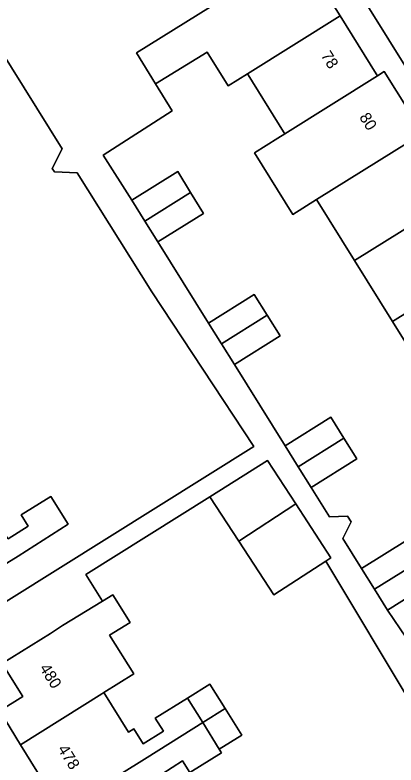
# Model space of a CAD drawing. Extents: x 159664 to 160323, y 385312 to 386115.
# Drawn here: x 159872.7 to 159905.9, y 385585.5 to 385650.9 of the extents above; entities that cross this region are included whole.
import ezdxf

# ---------------------------------------------------------------- set-up
doc = ezdxf.new("R2010")
doc.units = 0
for name, color, linetype in [('IMGEO_Erf', 7, 'Continuous'), ('IMGEO_Pand', 7, 'Continuous'), ('IMGEO_Pand_nummerreeks', 7, 'Continuous'), ('IMGEO_Voetpad_open', 7, 'Continuous')]:
    doc.layers.add(name, color=color, linetype=linetype)

msp = doc.modelspace()

# ---------------------------------------------------------------- linework, layer by layer
at = {"layer": 'IMGEO_Erf'}
for points in [[(159946.596, 385582.567), (159899.669, 385657.765), (159897.541, 385656.437), (159901.066, 385650.785), (159904.21, 385645.744), (159904.322, 385645.564), (159904.916, 385645.935), (159908.271, 385640.569)], [(159909.004, 385618.773), (159905.636, 385624.163), (159902.314, 385629.478), (159898.999, 385634.783), (159896.947, 385633.503), (159893.597, 385638.872), (159895.645, 385640.15), (159896.237, 385640.52), (159896.137, 385640.682), (159893.055, 385645.666), (159893.002, 385645.752), (159891.306, 385644.694), (159889.482, 385647.642), (159884.982, 385644.861), (159886.432, 385642.516), (159880.411, 385638.648), (159882.922, 385634.74), (159886.912, 385637.224), (159888.043, 385635.407), (159889.175, 385633.59), (159885.185, 385631.105), (159889.598, 385624.037), (159893.579, 385626.535), (159894.71, 385624.733), (159895.842, 385622.931), (159891.861, 385620.432), (159896.265, 385613.331), (159900.248, 385615.826), (159901.381, 385614.016), (159902.515, 385612.206), (159898.531, 385609.712), (159900.142, 385607.157), (159901.713, 385607.207), (159902.04, 385606.724), (159901.315, 385605.272), (159902.94, 385602.661), (159906.93, 385605.145)], [(159872.124, 385605.243), (159873.887, 385606.344), (159873.274, 385607.325), (159875.856, 385608.938), (159877.358, 385606.535), (159872.995, 385603.734), (159872.011, 385603.118)], [(159907.52, 385590.473), (159899.833, 385603.309), (159895.3, 385600.355), (159892.24, 385605.051), (159889.724, 385608.912), (159878.895, 385602.141), (159880.347, 385599.819), (159881.256, 385600.374), (159882.76, 385597.969), (159880.976, 385596.854), (159883.079, 385593.489), (159880.464, 385591.853), (159882.616, 385588.411), (159883.085, 385588.704), (159883.906, 385587.39), (159885.662, 385588.488), (159884.955, 385589.619), (159887.761, 385591.373), (159889.723, 385592.599), (159891.06, 385590.46), (159892.503, 385588.152), (159890.541, 385586.926), (159890.741, 385586.607), (159887.979, 385584.88), (159887.345, 385585.894), (159885.531, 385584.76)], [(159909.182, 385601.526), (159905.191, 385599.043), (159906.855, 385596.601)], [(159875.549, 385583.563), (159873.206, 385587.314), (159871.373, 385590.249), (159873.403, 385591.515), (159871.612, 385594.38), (159866.206, 385591), (159867.78, 385588.482), (159889.403, 385553.858)]]:
    msp.add_lwpolyline(points, dxfattribs=at)
msp.add_lwpolyline([(159884.653, 385626.763), (159878.162, 385637.111), (159876.173, 385637.213), (159875.976, 385637.489), (159876.848, 385639.206), (159870.177, 385649.841), (159864.753, 385646.292), (159863.207, 385648.655), (159868.631, 385652.204), (159868.368, 385652.606), (159839.054, 385634.423), (159863.871, 385594.734), (159893.561, 385613.299)], close=True, dxfattribs=at)
at = {"layer": 'IMGEO_Pand'}
for points in [[(159901.066, 385650.785), (159897.541, 385656.437), (159883.314, 385647.559), (159884.982, 385644.861), (159889.482, 385647.642), (159891.306, 385644.694), (159893.002, 385645.752)], [(159904.322, 385645.564), (159904.21, 385645.744), (159901.066, 385650.785), (159893.002, 385645.752), (159893.055, 385645.666), (159896.137, 385640.682), (159896.237, 385640.52)], [(159908.271, 385640.569), (159904.916, 385645.935), (159904.322, 385645.564), (159896.237, 385640.52), (159895.645, 385640.15), (159893.597, 385638.872), (159896.947, 385633.503), (159898.999, 385634.783), (159907.084, 385639.828)], [(159907.183, 385639.669), (159907.084, 385639.828), (159898.999, 385634.783), (159902.314, 385629.478), (159910.395, 385634.52)], [(159886.912, 385637.224), (159882.922, 385634.74), (159884.053, 385632.923), (159888.043, 385635.407)], [(159885.185, 385631.105), (159889.175, 385633.59), (159888.043, 385635.407), (159884.053, 385632.923)], [(159902.314, 385629.478), (159905.636, 385624.163), (159913.713, 385629.203), (159910.395, 385634.52)], [(159917.078, 385623.811), (159913.713, 385629.203), (159905.636, 385624.163), (159909.004, 385618.773)], [(159893.579, 385626.535), (159889.598, 385624.037), (159890.729, 385622.235), (159894.71, 385624.733)], [(159895.842, 385622.931), (159894.71, 385624.733), (159890.729, 385622.235), (159891.861, 385620.432)], [(159900.248, 385615.826), (159896.265, 385613.331), (159897.398, 385611.522), (159901.381, 385614.016)], [(159898.531, 385609.712), (159902.515, 385612.206), (159901.381, 385614.016), (159897.398, 385611.522)], [(159894.754, 385612.057), (159889.724, 385608.912), (159892.24, 385605.051), (159897.209, 385608.289)], [(159869.236, 385609.471), (159862.136, 385605.04), (159863.969, 385602.105), (159865.993, 385603.369), (159867.795, 385600.486), (159872.011, 385603.118), (159872.995, 385603.734), (159877.358, 385606.535), (159875.856, 385608.938), (159873.274, 385607.325), (159873.887, 385606.344), (159872.124, 385605.243), (159869.414, 385609.582)], [(159897.209, 385608.289), (159892.24, 385605.051), (159895.3, 385600.355), (159899.833, 385603.309), (159900.269, 385603.594)], [(159906.93, 385605.145), (159902.94, 385602.661), (159904.066, 385600.852), (159908.056, 385603.335)], [(159909.182, 385601.526), (159908.056, 385603.335), (159904.066, 385600.852), (159905.191, 385599.043)], [(159880.976, 385596.854), (159882.76, 385597.969), (159881.256, 385600.374), (159880.347, 385599.819), (159876.873, 385597.7), (159875.816, 385597.006), (159871.612, 385594.38), (159873.403, 385591.515), (159871.373, 385590.249), (159873.206, 385587.314), (159880.312, 385591.758), (159880.464, 385591.853), (159883.079, 385593.489)], [(159887.761, 385591.373), (159889.098, 385589.234), (159891.06, 385590.46), (159889.723, 385592.599)], [(159889.098, 385589.234), (159887.761, 385591.373), (159884.955, 385589.619), (159885.662, 385588.488), (159883.906, 385587.39), (159883.085, 385588.704), (159882.616, 385588.411), (159880.464, 385591.853), (159880.312, 385591.758), (159873.206, 385587.314), (159875.549, 385583.563), (159876.059, 385583.882), (159877.318, 385581.866), (159884.255, 385586.205)], [(159891.06, 385590.46), (159889.098, 385589.234), (159890.541, 385586.926), (159892.503, 385588.152)], [(159885.845, 385583.326), (159886.263, 385583.587), (159885.531, 385584.76), (159887.345, 385585.894), (159887.979, 385584.88), (159890.741, 385586.607), (159890.541, 385586.926), (159889.098, 385589.234), (159884.255, 385586.205), (159877.318, 385581.866), (159878.919, 385579.302), (159878.41, 385578.984), (159880.41, 385575.781), (159887.397, 385580.151), (159887.708, 385580.346)]]:
    msp.add_lwpolyline(points, close=True, dxfattribs=at)
at = {"layer": 'IMGEO_Voetpad_open'}
for points in [[(159870.48, 385704.729), (159868.229, 385703.363), (159879.357, 385685.561), (159879.997, 385685.936), (159882.47, 385682.008), (159884.023, 385682.836), (159897.553, 385661.156), (159899.669, 385657.765), (159946.596, 385582.567), (159948.717, 385579.169), (159962.464, 385557.14), (159964.577, 385558.015)], [(159906.855, 385596.601), (159905.191, 385599.043), (159904.066, 385600.852), (159902.94, 385602.661), (159901.315, 385605.272), (159902.04, 385606.724), (159901.713, 385607.207), (159900.142, 385607.157), (159898.531, 385609.712), (159897.398, 385611.522), (159896.265, 385613.331), (159891.861, 385620.432), (159890.729, 385622.235), (159889.598, 385624.037), (159885.185, 385631.105), (159884.053, 385632.923), (159882.922, 385634.74), (159880.411, 385638.648), (159886.432, 385642.516), (159884.982, 385644.861), (159883.314, 385647.559), (159897.541, 385656.437)], [(159868.631, 385652.204), (159870.177, 385649.841), (159876.848, 385639.206), (159875.976, 385637.489), (159876.173, 385637.213), (159878.162, 385637.111), (159884.653, 385626.763), (159893.561, 385613.299), (159863.871, 385594.734), (159866.206, 385591), (159871.612, 385594.38), (159875.816, 385597.006), (159876.873, 385597.7), (159880.347, 385599.819), (159878.895, 385602.141), (159889.724, 385608.912), (159894.754, 385612.057), (159897.209, 385608.289), (159900.269, 385603.594), (159899.833, 385603.309), (159907.52, 385590.473)]]:
    msp.add_lwpolyline(points, dxfattribs=at)

# ---------------------------------------------------------------- texts
at = {"layer": 'IMGEO_Pand_nummerreeks'}
for s, rotation, p in [('78', 301.9651, (159899.35, 385647.344)), ('80', 301.9651, (159902.702, 385641.973)), ('480', 302.01094, (159874.829, 385593.987)), ('478', 301.99075, (159876.416, 385586.932))]:
    msp.add_text(s, height=1, rotation=rotation, dxfattribs=at).set_placement(p)

doc.saveas('drawing.dxf')
